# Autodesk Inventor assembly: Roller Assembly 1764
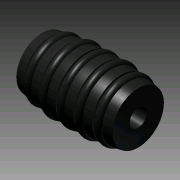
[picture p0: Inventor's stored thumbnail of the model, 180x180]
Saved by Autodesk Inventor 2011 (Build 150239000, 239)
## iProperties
Created: 2007-11
Part Number: Roller Assembly 1764
Document SubType Name: Assembly
Designer: lwoods
Author: lwoods
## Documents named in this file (4)
- R:\CAD Archives\Wheels\Omniwheel 1764\Roller Assembly 1764.iam
- R:\CAD Archives\Wheels\Omniwheel 1764\RollerRidges 1764.ipt
- R:\CAD Archives\Wheels\Omniwheel 1764\O Ring 1 R.609 1764.ipt
- R:\CAD Archives\Wheels\Omniwheel 1764\O Ring 2 R.671 1764.ipt
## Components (6 placed, 3 different names)
1. RollerRidges 1764:1 — Mate:2, Mate:7, Mate:11, Mate:16, Mate:19, Mate:25
2. O Ring 1 R.609 1764:1 — Mate:4, Angle:1, Mate:6
3. O Ring 1 R.609 1764:2 — Mate:8, Angle:2, Mate:9
4. O Ring 2 R.671 1764:1 — Mate:13, Angle:3, Mate:14
5. O Ring 2 R.671 1764:2 — Mate:12, Angle:4, Mate:17
6. O Ring 2 R.671 1764:3 — Mate:20, Angle:6, Mate:23
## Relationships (21: Mate 16, Angle 5)
- Mate:2: RollerRidges 1764:1
- Mate:4: O Ring 1 R.609 1764:1
- Angle:1: O Ring 1 R.609 1764:1
- Mate:6: O Ring 1 R.609 1764:1
- Mate:7: RollerRidges 1764:1
- Mate:8: O Ring 1 R.609 1764:2
- Angle:2: O Ring 1 R.609 1764:2
- Mate:9: O Ring 1 R.609 1764:2
- Mate:11: RollerRidges 1764:1
- Mate:12: O Ring 2 R.671 1764:2
- Mate:13: O Ring 2 R.671 1764:1
- Angle:3: O Ring 2 R.671 1764:1
- Mate:14: O Ring 2 R.671 1764:1
- Mate:16: RollerRidges 1764:1
- Angle:4: O Ring 2 R.671 1764:2
- Mate:17: O Ring 2 R.671 1764:2
- Mate:19: RollerRidges 1764:1
- Mate:20: O Ring 2 R.671 1764:3
- Angle:6: O Ring 2 R.671 1764:3
- Mate:23: O Ring 2 R.671 1764:3
- Mate:25: RollerRidges 1764:1
